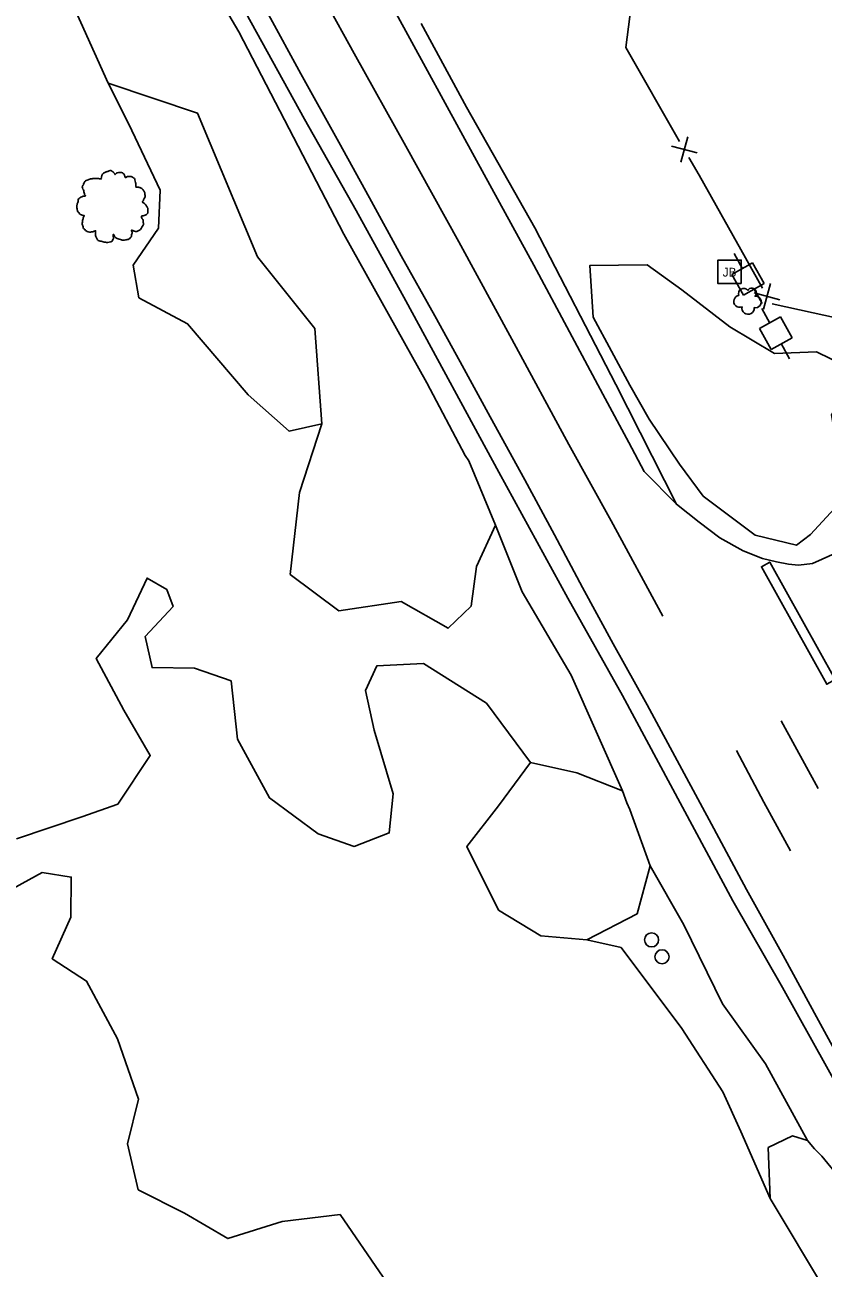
# Model space of a CAD drawing. Extents: x 2160437 to 2172832, y 205694 to 212444.
# Drawn here: x 2171630.1 to 2171800.7, y 206184.5 to 206449.9 of the extents above; entities that cross this region are included whole.
import ezdxf

# ---------------------------------------------------------------- set-up
doc = ezdxf.new("R2010")
doc.units = 0
for name, color, linetype in [('Default', 7, 'Continuous'), ('RD_EX_DR_Inlet', 7, 'Continuous'), ('RD_EX_Fence_Other', 7, 'Continuous'), ('RD_EX_LaneStripe', 7, 'Continuous'), ('RD_EX_ParkingStripe', 7, 'Continuous'), ('RD_EX_Road', 7, 'Continuous'), ('RD_EX_Road_Post', 7, 'Continuous'), ('RD_EX_UT', 7, 'Continuous'), ('RD_EX_VEG', 7, 'Continuous'), ('RD_EX_VEG_ShrubLine', 7, 'Continuous'), ('RD_EX_VEG_TreeLine', 7, 'Continuous')]:
    doc.layers.add(name, color=color, linetype=linetype)

# ---------------------------------------------------------------- blocks, each defined once
blk = doc.blocks.new('RD_EX_Fnce_Other')
at = {"layer": 'Default'}
for points in [[(-0.0417, -0.0417), (0.0417, 0.0417)], [(-0.0417, 0.0417), (0.0417, -0.0417)]]:
    blk.add_lwpolyline(points, dxfattribs=at)
blk = doc.blocks.new('POST')
at = {"layer": 'Default'}
for start, end in [(90, 270), (270, 90)]:
    blk.add_arc((0, 0), 0.0417, start, end, dxfattribs=at)
blk = doc.blocks.new('T2')
at = {"layer": 'RD_EX_VEG'}
for points in [[(0.05, 7.21), (-0.25, 7.24), (-0.57, 7.14), (-0.82, 7.04), (-1.05, 6.96), (-1.27, 6.86), (-1.57, 6.69), (-1.8, 6.49), (-1.92, 6.24), (-1.97, 6.01), (-2.02, 5.74), (-2.02, 5.56), (-2.15, 5.54), (-2.3, 5.56), (-2.55, 5.64), (-2.8, 5.64), (-3.05, 5.64), (-3.4, 5.61), (-3.75, 5.61), (-4.02, 5.56), (-4.35, 5.51), (-4.72, 5.39), (-5.07, 5.26), (-5.37, 5.01), (-5.62, 4.54), (-5.75, 4.19), (-5.9, 3.94), (-5.75, 3.49), (-5.57, 3.14), (-5.55, 2.94), (-5.47, 2.52), (-5.37, 2.29), (-5.25, 2.09), (-5.32, 2.07), (-5.7, 2.02), (-6, 1.92), (-6.42, 1.69), (-6.64, 1.47), (-6.74, 1.14), (-6.77, 0.79), (-6.87, 0.59), (-6.94, 0.32), (-6.97, 0.24), (-7.02, -0.08), (-6.92, -0.53), (-6.89, -0.88), (-6.77, -1.11), (-6.62, -1.28), (-6.44, -1.53), (-6.05, -1.76), (-5.72, -1.86), (-5.52, -1.88), (-5.7, -2.38), (-5.75, -2.73), (-5.87, -3.13), (-5.87, -3.21), (-5.92, -3.68), (-5.77, -4.01), (-5.7, -4.38), (-5.52, -4.61), (-5.25, -4.91), (-4.92, -5.13), (-4.42, -5.26), (-4.02, -5.23), (-3.45, -5.06), (-3.2, -4.98), (-3.22, -5.16), (-3.2, -5.53), (-3.2, -5.96), (-3.05, -6.28), (-2.95, -6.56), (-2.8, -6.81), (-2.47, -7.03), (-2.07, -7.11), (-1.65, -7.26), (-1.2, -7.33), (-0.7, -7.36), (-0.1, -7.21), (0.18, -7.08), (0.28, -6.91), (0.48, -6.53), (0.43, -6.31), (0.45, -5.71), (0.55, -5.88), (0.73, -6.23), (1.23, -6.53), (1.63, -6.71), (2.1, -6.86), (2.4, -6.93), (2.88, -6.86), (3.25, -6.78), (3.63, -6.66), (3.93, -6.38), (4.1, -6.11), (4.15, -5.83), (4.23, -5.46), (4.28, -5.28)], [(4.28, -5.28), (4.2, -5.11), (4.15, -4.86), (4.23, -4.88), (4.4, -4.93), (4.68, -5.06), (4.9, -5.13), (5.23, -5.11), (5.5, -5.01), (5.95, -4.73), (6.22, -4.26), (6.5, -3.86), (6.57, -3.53), (6.52, -3.31), (6.5, -2.81), (6.3, -2.56), (6.25, -2.43), (6.15, -2.03), (6.22, -1.98), (6.5, -1.93), (6.87, -1.81), (7.15, -1.68), (7.37, -1.51), (7.45, -1.28), (7.42, -0.88), (7.47, -0.48), (7.4, -0.33), (7.3, -0.18), (7.22, 0.02), (7.07, 0.17), (6.97, 0.32), (6.87, 0.42), (6.75, 0.57), (6.57, 0.69), (6.42, 0.74), (6.37, 0.89), (6.52, 1.09), (6.57, 1.19), (6.6, 1.42), (6.82, 1.77), (6.87, 2.17), (6.82, 2.59), (6.77, 2.87), (6.62, 3.14), (6.42, 3.39), (6.3, 3.56), (6.12, 3.69), (5.8, 3.81), (5.55, 3.86), (5.2, 3.86), (5, 3.91), (5.03, 3.96), (5.03, 4.11), (5.03, 4.39), (4.95, 4.84), (4.8, 5.34), (4.8, 5.36), (4.7, 5.61), (4.48, 5.81), (4.3, 5.91), (4.1, 6.04), (3.85, 6.06), (3.55, 6.06), (3.28, 6.01), (3.08, 5.91), (2.9, 5.79), (2.83, 5.94), (2.73, 6.24), (2.68, 6.39), (2.53, 6.56), (2.3, 6.76), (1.85, 6.89), (1.23, 6.81), (0.93, 6.61), (0.78, 6.44), (0.73, 6.56), (0.53, 6.76), (0.43, 6.94), (0.25, 7.06), (0.1, 7.16), (0, 7.21)]]:
    blk.add_spline(points, degree=3, dxfattribs=at)
blk = doc.blocks.new('PP')
at = {"layer": 'RD_EX_UT'}
for p, q in [((2.49, 2.51), (-2.51, 2.51)), ((-2.51, 2.51), (-2.51, -2.49)), ((2.49, -2.49), (2.49, 2.51)), ((-5.94, -0.05), (-2.47, -0.05)), ((-2.51, -2.49), (2.49, -2.49)), ((2.42, -0.05), (6.06, -0.05))]:
    blk.add_line(p, q, dxfattribs=at)

msp = doc.modelspace()

# ---------------------------------------------------------------- linework, layer by layer
at = {"layer": 'RD_EX_DR_Inlet'}
msp.add_line((2171783.18, 206394.66), (2171783.18, 206399.66), dxfattribs=at)
msp.add_lwpolyline([(2171783.18, 206394.66), (2171783.18, 206399.66), (2171778.18, 206399.66), (2171778.18, 206394.66)], close=True, dxfattribs=at)
at = {"layer": 'RD_EX_Fence_Other'}
for points in [[(2171770.01, 206425.01), (2171758.49, 206445.01), (2171759.67, 206453.84)], [(2171787.7, 206393.65), (2171774.17, 206417.78), (2171772.01, 206421.54)], [(2171815.1, 206376.7), (2171813.8, 206376.49), (2171809.57, 206386.01), (2171789.75, 206390.3)]]:
    msp.add_lwpolyline(points, dxfattribs=at)
at = {"layer": 'RD_EX_LaneStripe'}
for points in [[(2171766.42, 206323.67), (2171755.36, 206344), (2171746.35, 206360.28), (2171734.2, 206382.78), (2171722.83, 206403.55), (2171711.5, 206423.95), (2171700.51, 206443.79), (2171688.38, 206465.77)], [(2171799.59, 206286.86), (2171791.67, 206301.32)], [(2171793.7, 206273.52), (2171787.98, 206283.92), (2171782.13, 206294.94)]]:
    msp.add_lwpolyline(points, dxfattribs=at)
at = {"layer": 'RD_EX_ParkingStripe'}
msp.add_lwpolyline([(2171803.22, 206310.12), (2171789.26, 206335.21), (2171787.47, 206334.21), (2171801.43, 206309.13)], close=True, dxfattribs=at)
at = {"layer": 'RD_EX_Road'}
for points in [[(2171901.39, 206044.47), (2171876.6, 206089.89), (2171865.46, 206109.54), (2171853.29, 206132.68), (2171840.93, 206155.1), (2171828.92, 206176.69), (2171815.72, 206201.3), (2171804.53, 206221.91), (2171792.02, 206244.4), (2171781.36, 206262.89), (2171770.61, 206282.85), (2171757.79, 206306.7), (2171746.12, 206327.48), (2171731.4, 206354.36), (2171711.51, 206390.94), (2171700.93, 206410.28), (2171689.86, 206429.77), (2171676.21, 206454.51)], [(2171836.45, 206170.39), (2171827.66, 206186.35), (2171817.1, 206205.56), (2171807.83, 206222.34), (2171799.68, 206237.32), (2171792.13, 206251.21), (2171784.29, 206265.31), (2171777.35, 206278.32), (2171770.46, 206291), (2171763.06, 206304.69), (2171755.78, 206317.77), (2171749.27, 206329.78), (2171743.28, 206340.99), (2171736.95, 206352.74), (2171729.52, 206366.17), (2171723.11, 206377.94), (2171717.71, 206387.79), (2171710.52, 206400.59), (2171703.76, 206412.95), (2171697.2, 206424.8), (2171689.07, 206439.41), (2171682.16, 206452.06)], [(2171803.95, 206337.4), (2171798.39, 206334.86), (2171795.38, 206334.51), (2171793.3, 206334.72), (2171790.7, 206335.26), (2171787.69, 206335.95), (2171783.56, 206337.57), (2171778.58, 206340.34), (2171774.19, 206343.69), (2171769.37, 206347.58), (2171762.47, 206354.54), (2171759.17, 206360.7), (2171753.64, 206371.03), (2171746.5, 206384.37), (2171738.87, 206398.61), (2171726.65, 206420.94), (2171709.03, 206453.07)], [(2171714.82, 206450.19), (2171724.5, 206432.33), (2171739.05, 206406.54), (2171756.35, 206373.11), (2171769.37, 206347.58)]]:
    msp.add_lwpolyline(points, dxfattribs=at)
at = {"layer": 'RD_EX_VEG'}
for centre, radius, start, end in [((2171783.67, 206392.55), 1.08, 34.9763, 204.756), ((2171785.44, 206392.7), 0.995, 308.7626, 152.0467), ((2171782.83, 206390.84), 1.26, 96.4518, 294.734), ((2171786.23, 206390.72), 1.22, 256.5667, 98.1046), ((2171784.64, 206389.4), 1.32, 166.8827, 5.7589)]:
    msp.add_arc(centre, radius, start, end, dxfattribs=at)
at = {"layer": 'RD_EX_VEG_ShrubLine'}
for points in [[(2171647.96, 206437.46), (2171652.37, 206428.66), (2171659.05, 206414.56), (2171658.66, 206406.49), (2171653.3, 206398.57), (2171654.48, 206391.61), (2171664.89, 206386.07), (2171677.83, 206370.91), (2171686.57, 206363.14), (2171693.61, 206364.72)], [(2171730.66, 206343.09), (2171736.38, 206328.81), (2171746.82, 206311.07), (2171757.8, 206286.34)], [(2171738.13, 206292.4), (2171728.75, 206305.07), (2171715.29, 206313.51), (2171705.34, 206313.05), (2171702.9, 206307.75), (2171704.79, 206299.28), (2171708.84, 206285.75), (2171707.98, 206277.36), (2171700.45, 206274.51), (2171692.79, 206277.18), (2171682.41, 206284.85), (2171675.56, 206297.42), (2171674.2, 206309.82), (2171666.36, 206312.57), (2171657.3, 206312.67), (2171655.87, 206319.33), (2171661.8, 206325.7), (2171660.46, 206329.31), (2171656.25, 206331.79), (2171652.05, 206322.9), (2171645.36, 206314.63), (2171651.29, 206303.55), (2171656.91, 206293.9), (2171649.98, 206283.49), (2171642.32, 206280.81), (2171628.37, 206276.09)], [(2171624.59, 206263.91), (2171633.87, 206268.95), (2171640.04, 206267.94), (2171639.97, 206259.4), (2171635.99, 206250.53), (2171643.33, 206245.76), (2171649.95, 206233.4), (2171654.42, 206220.53), (2171652.07, 206211.01), (2171654.31, 206201.2), (2171664.22, 206196.21), (2171673.49, 206190.77), (2171685.12, 206194.41), (2171697.48, 206195.9), (2171706.66, 206182.57)], [(2171763.7, 206270.37), (2171770.91, 206257.77), (2171779.19, 206240.92), (2171788.34, 206228.05), (2171797.31, 206211.71)], [(2171789.35, 206199.34), (2171783.06, 206213.67), (2171779.22, 206222.07), (2171770.48, 206235.6), (2171757.49, 206252.91), (2171750.22, 206254.55)]]:
    msp.add_lwpolyline(points, dxfattribs=at)
at = {"layer": 'RD_EX_VEG_TreeLine'}
msp.add_lwpolyline([(2171651.74, 206489.44), (2171675.84, 206448.42), (2171698.28, 206405.16), (2171715.99, 206373.49), (2171724.23, 206357.94), (2171725, 206356.82), (2171730.66, 206343.09), (2171726.6, 206334.27), (2171725.49, 206325.8), (2171720.53, 206321.07), (2171710.5, 206326.79), (2171697.18, 206324.8), (2171686.81, 206332.56), (2171688.78, 206350.04), (2171693.61, 206364.72), (2171692.08, 206385.09), (2171679.85, 206400.34), (2171667.03, 206431.04), (2171647.96, 206437.46), (2171633.35, 206469.85)], dxfattribs=at)
for points in [[(2171763.53, 206365.7), (2171759.38, 206372.96), (2171751.52, 206387.48), (2171750.82, 206398.49), (2171763.07, 206398.63), (2171770.46, 206393.31), (2171780.71, 206385.38), (2171790.28, 206379.69), (2171799.22, 206380.07), (2171808.14, 206375.75), (2171802.44, 206366.62), (2171803.85, 206358.06), (2171803.09, 206346.65), (2171797.96, 206341.09), (2171795, 206338.82), (2171786.15, 206340.97), (2171775.01, 206349.3), (2171770.01, 206356.09)], [(2171759.4, 206282.4), (2171763.7, 206270.37), (2171760.91, 206260.11), (2171750.22, 206254.55), (2171740.37, 206255.44), (2171731.33, 206260.89), (2171724.54, 206274.49), (2171731.3, 206283.14), (2171738.13, 206292.4), (2171748.02, 206290.2), (2171757.8, 206286.34), (2171758.75, 206283.77)], [(2171800.41, 206208.4), (2171812.38, 206193.79), (2171822.52, 206175.87), (2171820.25, 206163.95), (2171812.17, 206169.17), (2171801.14, 206179.59), (2171789.35, 206199.34), (2171788.93, 206210.22), (2171794.15, 206212.74), (2171797.31, 206211.71), (2171798.85, 206209.94)]]:
    msp.add_lwpolyline(points, close=True, dxfattribs=at)

# ---------------------------------------------------------------- block references
at = {"layer": 'RD_EX_Fence_Other'}
for p, xscale, yscale, rotation in [((2171771.01, 206423.27), 48, 48, 119.94605), ((2171788.68, 206391.91), 47.99999999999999, 48.00000000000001, 119.271778)]:
    msp.add_blockref('RD_EX_Fnce_Other', p, dxfattribs=dict(at, xscale=xscale, yscale=yscale, rotation=rotation))
at = {"layer": 'RD_EX_Road_Post', "xscale": 36, "yscale": 36}
for p in [(2171764.03, 206254.54), (2171766.25, 206250.93)]:
    msp.add_blockref('POST', p, dxfattribs=at)
at = {"layer": 'RD_EX_UT'}
for p, xscale, yscale, rotation in [((2171784.62, 206395.65), 1.02, 1.0199999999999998, 119.44438500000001), ((2171790.55, 206384.04), 1.0199999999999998, 1.02, -61.07455800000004)]:
    msp.add_blockref('PP', p, dxfattribs=dict(at, xscale=xscale, yscale=yscale, rotation=rotation))
at = {"layer": 'RD_EX_VEG', "xscale": 1.0499999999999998, "yscale": 1.0499999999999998}
msp.add_blockref('T2', (2171648.59, 206411.16), dxfattribs=at)

# ---------------------------------------------------------------- texts
at = {"layer": 'RD_EX_DR_Inlet'}
msp.add_text('JB', height=1.875, dxfattribs=at).set_placement((2171779.21, 206396.14))

doc.saveas('drawing.dxf')
